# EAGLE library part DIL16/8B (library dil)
SOCKET Dual In Line, 8 pins used
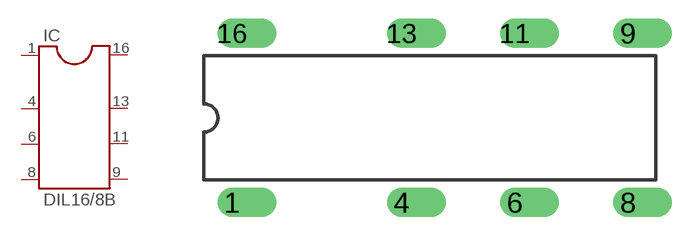
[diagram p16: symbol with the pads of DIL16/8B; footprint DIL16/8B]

Designator prefix IC

## DIL16/8B  [DIL16/8B]
1  1  pas
4  4  pas
6  6  pas
8  8  pas
9  9  pas
11  11  pas
13  13  pas
16  16  pas

## Footprint DIL16/8B (pad centres in mm)
SOCKET Dual In Line, 8 pins used
drill 0.813 offset: 1 -8.89,-3.81; 4 -1.27,-3.81; 6 3.81,-3.81; 8 8.89,-3.81; 9 8.89,3.81; 11 3.81,3.81; 13 -1.27,3.81; 16 -8.89,3.81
